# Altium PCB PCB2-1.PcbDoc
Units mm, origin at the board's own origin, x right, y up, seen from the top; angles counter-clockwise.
Board outline 38 x 28 mm, 2 copper layers (Top Layer, Bottom Layer); 5 components, 0 nets, 14 pads, 9 vias.
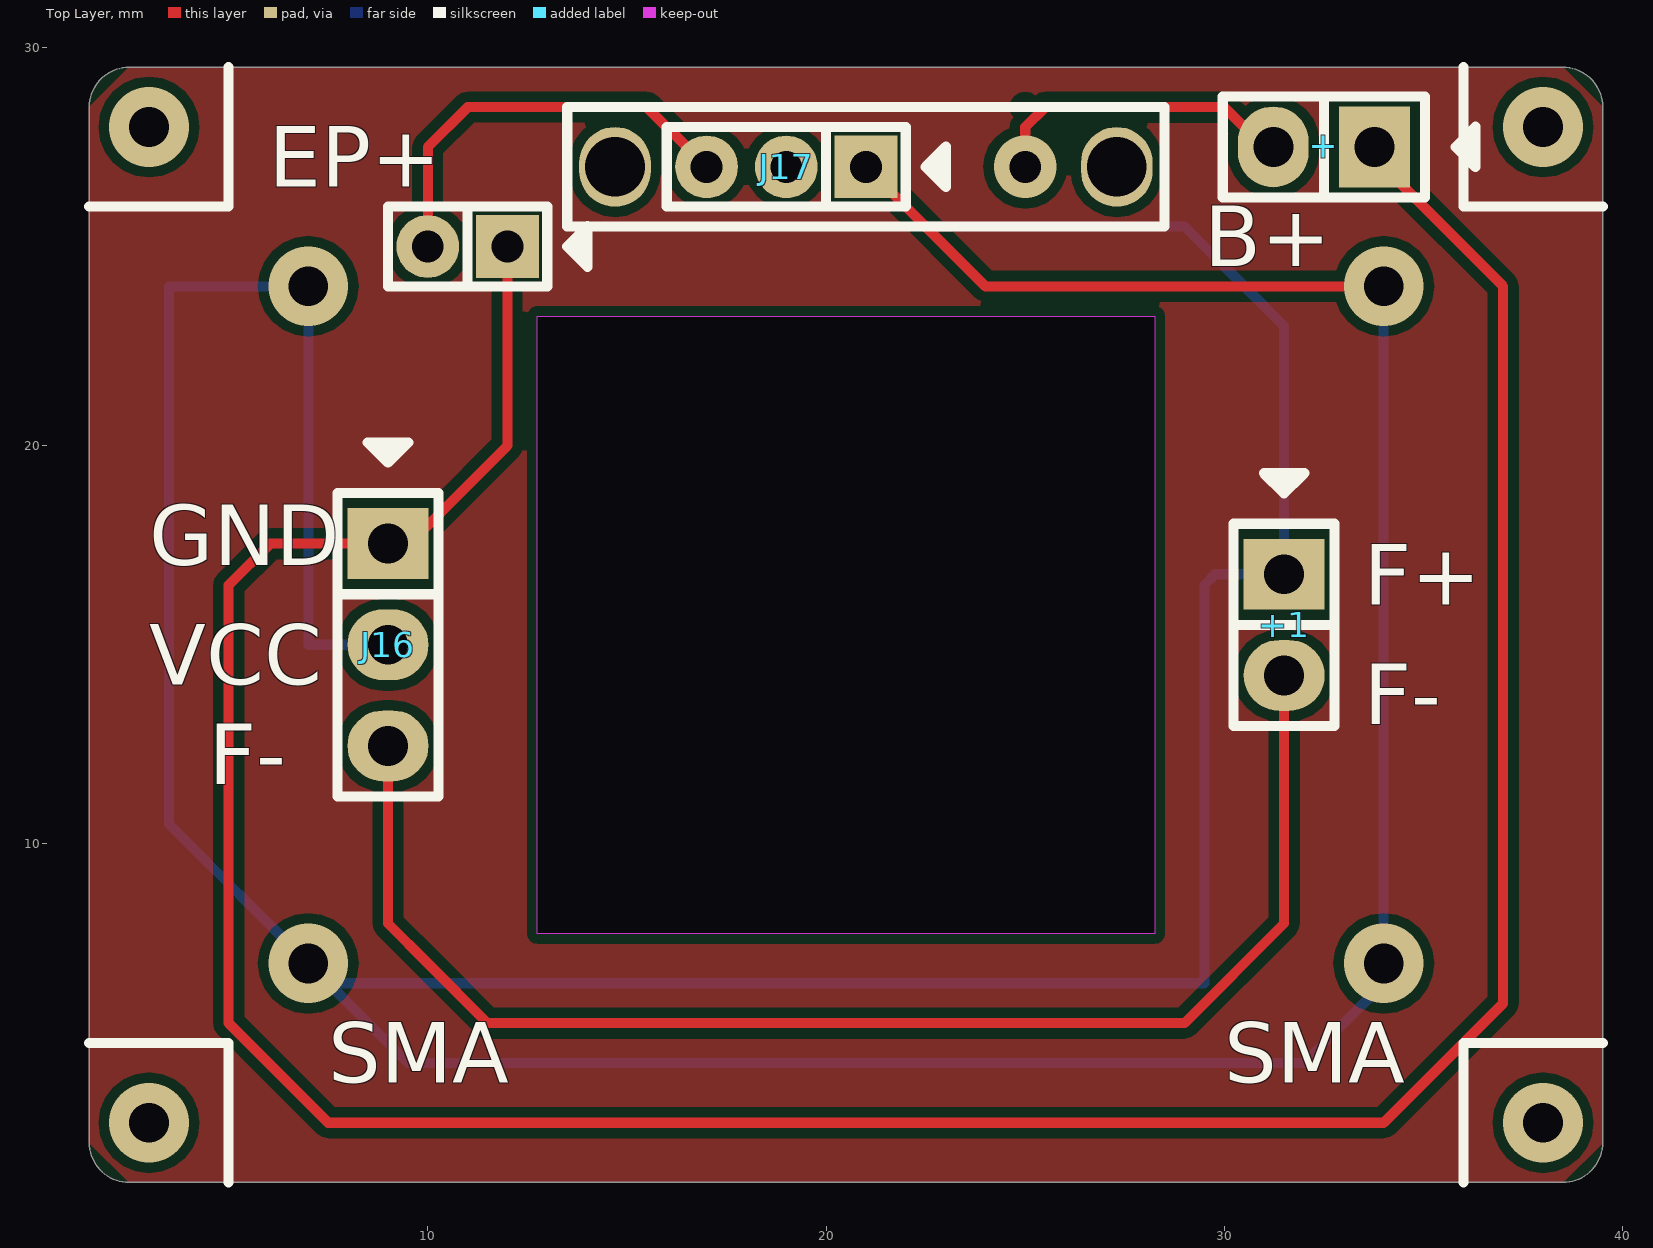
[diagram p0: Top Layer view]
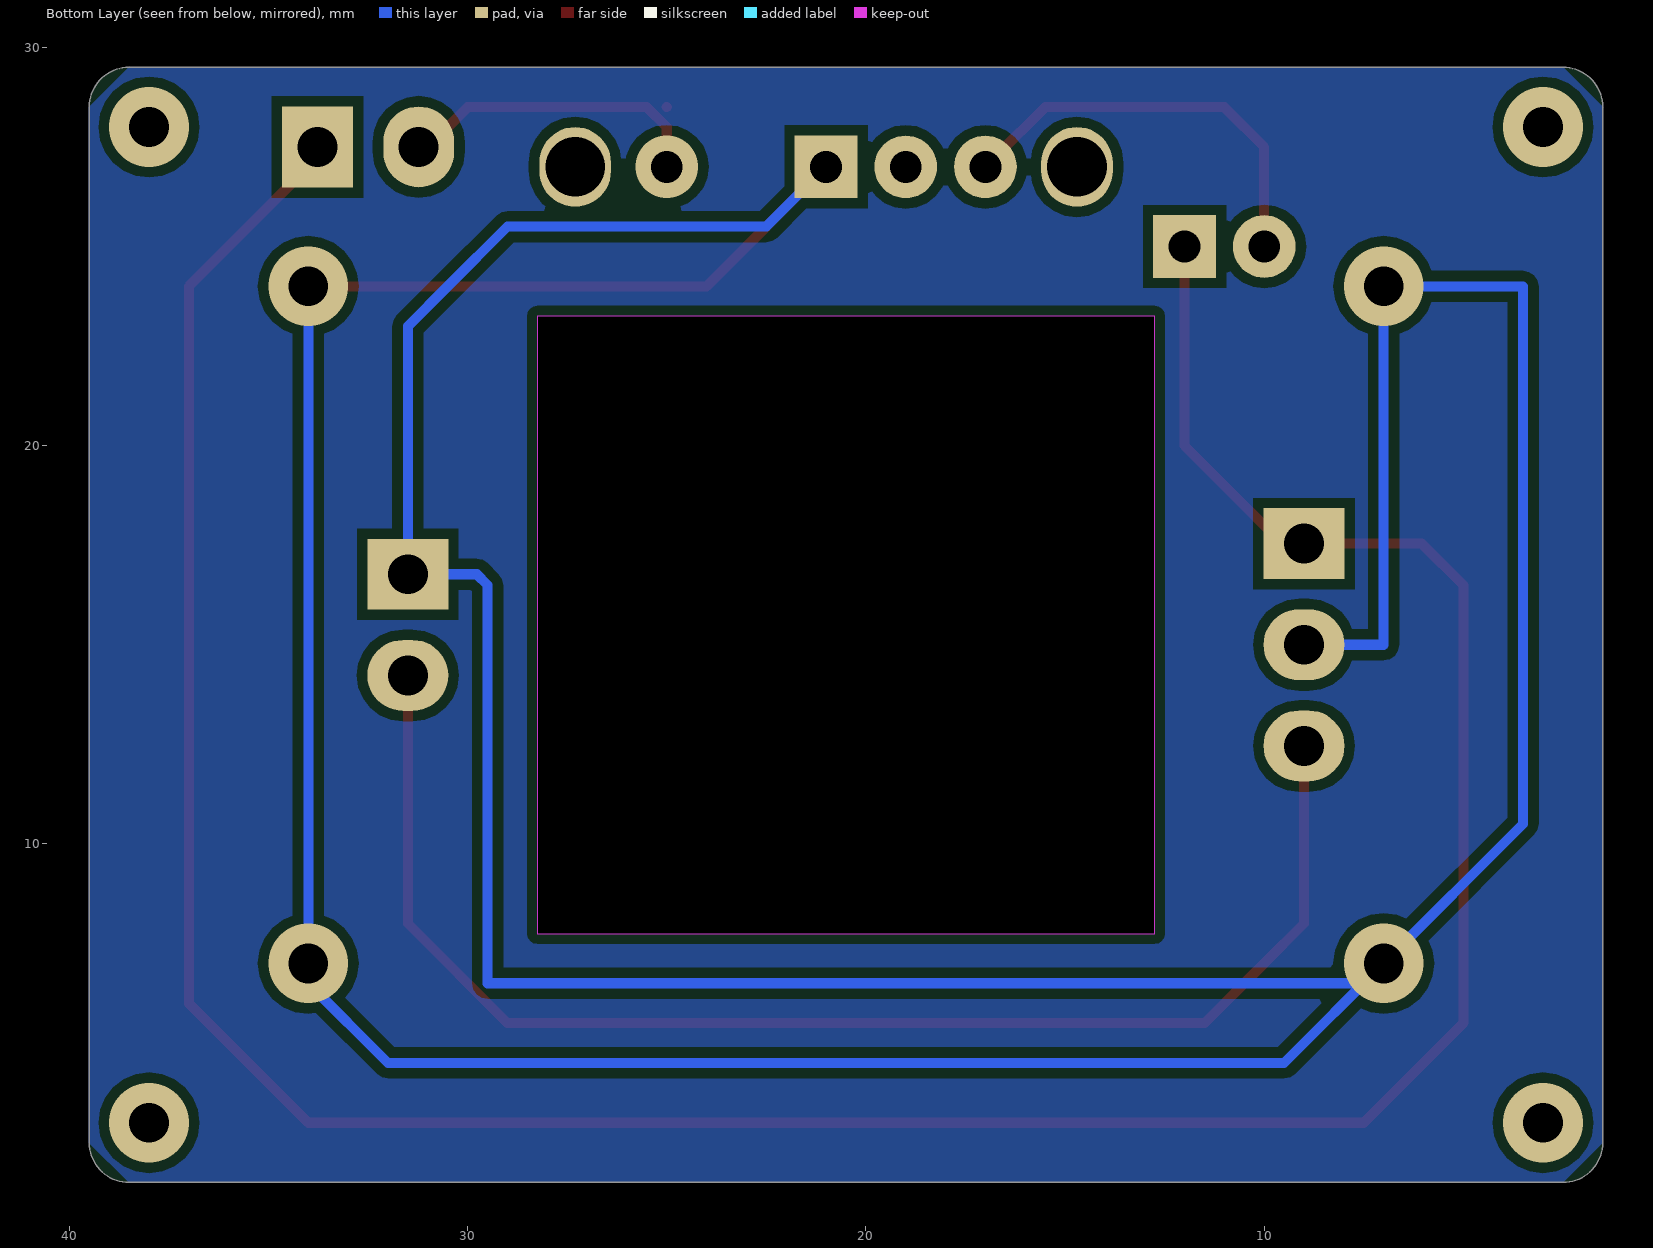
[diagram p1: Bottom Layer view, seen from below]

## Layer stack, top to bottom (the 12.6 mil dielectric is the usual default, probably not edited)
Top Solder: solder mask 0.0102, Solder Resist, Dk 3.5
Top Layer: signal copper 0.0356
Dielectric 1: dielectric 0.32, FR-4, Dk 4.8
Bottom Layer: signal copper 0.0356
Bottom Solder: solder mask 0.0102, Solder Resist, Dk 3.5

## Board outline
1.5,2.5 1.5,28.5 cw(c2.5,28.5) 2.5,29.5 38.5,29.5 cw(c38.5,28.5) 39.5,28.5 39.5,2.5 cw(c38.5,2.5) 38.5,1.5 2.5,1.5 cw(c2.5,2.5)
cut-out: 12.75,23.25 28.25,23.25 28.25,7.75 12.75,7.75

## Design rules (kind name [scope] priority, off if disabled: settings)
Clearance [All] p1: gap=0.254
PolygonConnect [All] p1: connectstyle=Relief reliefconductorwidth=0.254 reliefentries=4 polygonreliefangle="90 Angle" airgapwidth=0.254
RoutingVias [All] p1: holewidth=0.711 width=1.27 viastyle="Through Hole" minholewidth=0.711 minwidth=1.27 maxholewidth=0.711 maxwidth=1.27
SolderMaskExpansion [All] p1: expansion=0.102
Width [All] p1: maxlimit=0.254 minlimit=0.254 preferedwidth=0.254
29 further rules are at their usual default settings.

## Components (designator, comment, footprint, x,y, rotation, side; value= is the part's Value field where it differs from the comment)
+ "Comment" PIN-2-2.54-1.0 32.5,27.5 r180 top
+1 "Comment" PIN-2-2.54-1.0 31.5,15.5 r270 top
EP+ "Comment" PIN-2-2.0-0.8 11,25 r180 top
J16 "Comment" PIN-3-2.54-1.0 9,15 r270 top
J17 "Comment" PIN-3-2.0-0.8 19,27 r180 top

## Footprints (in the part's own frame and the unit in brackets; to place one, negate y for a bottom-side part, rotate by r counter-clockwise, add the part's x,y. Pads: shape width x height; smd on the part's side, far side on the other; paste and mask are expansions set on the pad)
PIN-2-2.0-0.8 [mm] "Pin Header"
  rect 1.575x1.575 hole 0.8: 1(-1,0)
  round 1.575 hole 0.8: 2(1,0)
  silkscreen extent -3.01,-1 2,1, body extent -2,-1 2,1, height 5.31
PIN-2-2.54-1.0 [mil] "Pin Header"
  rect 70x80 hole 39.37: 1(-50,0)
  oval 70x80 hole 39.37: 2(50,0)
  silkscreen extent -150,-50 100,50, body extent -100,-50 100,50, height 398
PIN-3-2.0-0.8 [mil] "Pin Header"
  rect 62x62 hole 31.5: 1(-78.74,0)
  round 62 hole 31.5: 2(0,0) 3(78.74,0)
  silkscreen extent -158,-39 118,39, body extent -118,-39 118,39, height 209
PIN-3-2.54-1.0 [mil] "Pin Header"
  rect 70x80 hole 39.37: 1(-100,0)
  oval 70x80 hole 39.37: 2(0,0) 3(100,0)
  silkscreen extent -200,-50 150,50, body extent -150,-50 150,50, height 398

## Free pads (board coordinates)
  oval 1.8x2 hole 1.5: 0(14.7,27) 0(27.3,27)

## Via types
v1: diameter 2, hole 1, Top Layer to Bottom Layer, 8 vias
v2: diameter 1.575, hole 0.8, Top Layer to Bottom Layer, 1 vias

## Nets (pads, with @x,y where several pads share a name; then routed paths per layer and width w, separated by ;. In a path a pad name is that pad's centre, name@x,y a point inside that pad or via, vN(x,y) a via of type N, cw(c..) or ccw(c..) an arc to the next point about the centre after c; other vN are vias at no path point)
pads on no net: +1.1 +1.2 +.1 +.2 EP+.1 EP+.2 J16.1 J16.2 J16.3 J17.1 J17.2 J17.3
copper on no net: | length 282.5
  Top Layer w0.254: 9,12.46 9,8 10,7 11.5,5.5 15.125,5.5 25.375,5.5 29,5.5 31.5,8 31.5,14.23 ; 10,25 10,27.5 11,28.5 15.5,28.5 16.75,27.25 17.25,27.25 ; 12,25 12,20 9.54,17.54 9,17.54 6.04,17.54 5,16.5 5,5.5 7.5,3 34,3 37,6 37,24 33.635,27.365 ; 21,27 24,24 v1(34,24) ; v2(25,27) 25,28 25.5,28.5 27.558,28.5 30,28.5 31,27.5 31.23,27.5
  Bottom Layer w0.254: 9,15 7,15 v1(7,24) 3.5,24 3.5,10.5 v1(7,7) ; 21,26.5 21,27 22.5,25.5 29,25.5 30.5,24 31.5,23 31.5,22.5 31.5,16.77 29.77,16.77 29.5,16.5 29.5,6.5 7.5,6.5 v1(7,7) ; v1(34,24) v1(34,7) 34,6.5 32,4.5 30,4.5 23.75,4.5 17,4.5 9.5,4.5 v1(7,7)
  other v1: 3,3 38,3 3,28 38,28

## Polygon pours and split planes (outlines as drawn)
no net on Bottom Layer "Top Layer-No Net" (solid, pour order 4): 1.491,28.5 2.491,29.5 2.5,29.5 38.491,29.5 38.5,29.509 39.509,28.5 39.509,2.5 38.509,1.5 38.5,1.5 2.509,1.5 2.5,1.491 1.5,2.491 1.5,2.5 1.5,28.491 1.491,28.5
no net on Top Layer "Top Layer-No Net" (solid, pour order 6): 1.491,28.5 2.491,29.5 2.5,29.5 38.491,29.5 38.5,29.509 39.5,28.509 39.5,28.5 39.5,2.509 39.509,2.5 38.5,1.491 2.5,1.491 1.491,2.5 1.491,28.5

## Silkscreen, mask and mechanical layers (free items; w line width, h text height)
Top Overlay:
  lines w0.254: 1.5,5 5,5 5,1.5 ; 1.5,26 5,26 5,29.5 ; 36,1.5 36,5 39.5,5 ; 36,29.5 36,26 39.5,26 ; 13.5,25.5 28.5,25.5 28.5,28.5 13.5,28.5 13.5,25.5
  text "B+" at 29.5,24.5 h1.52
  text "GND" at 3,17 h1.52
  text "F+" at 33.5,16 h1.52
  text "VCC" at 3,14 h1.52
  text "F-" at 33.5,13 h1.52
  text "F-" at 4.5,11.5 h1.52
  text "SMA" at 7.5,4 h1.52
  text "SMA" at 30,4 h1.52
Mechanical 1:
  lines w0.254: 1.5,2.5 ccw(c2.5,2.5) 2.5,1.5 38.5,1.5 ccw(c38.5,2.5) 39.5,2.5 39.5,28.5 ccw(c38.5,28.5) 38.5,29.5 2.5,29.5 ccw(c2.5,28.5) 1.5,28.5 1.5,2.5 ; 12.75,7.75 12.75,23.25 28.25,23.25 28.25,7.75 12.75,7.75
